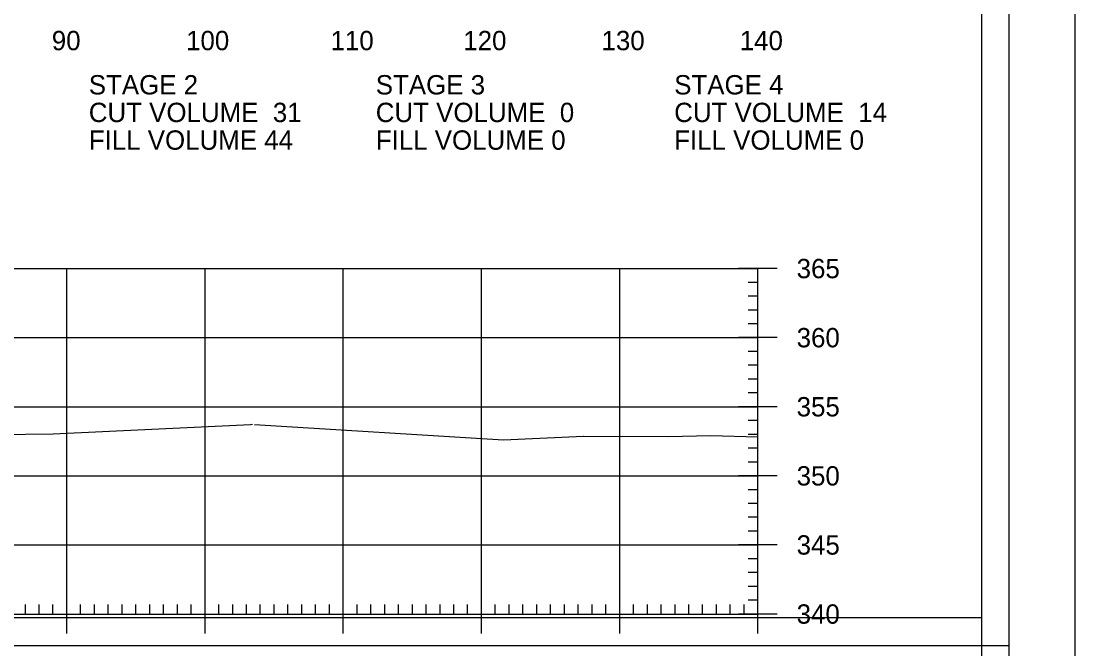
# Model space of a CAD drawing. Extents: x 1368910 to 1369601, y 380116 to 380950.
# Drawn here: x 1369524.3 to 1369600.5, y 380416.9 to 380462.3 of the extents above; entities that cross this region are included whole.
import ezdxf

# ---------------------------------------------------------------- set-up
doc = ezdxf.new("R2010")
doc.units = 0
for name, color, linetype in [('R_Axis', 7, 'Continuous'), ('R_Axis Annot', 7, 'Continuous'), ('R_Border', 7, 'Continuous'), ('R_Border Plan-Plan', 7, 'Continuous'), ('R_Exist Surface', 7, 'Continuous'), ('R_Grid', 7, 'Continuous'), ('R_No Plot', 7, 'Continuous')]:
    doc.layers.add(name, color=color, linetype=linetype)

msp = doc.modelspace()

# ---------------------------------------------------------------- linework, layer by layer
at = {"layer": 'R_Axis'}
for p, q in [((1369578.99, 380444.421), (1369576.19, 380444.421)), ((1369577.59, 380419.421), (1369577.59, 380444.421)), ((1369577.59, 380443.421), (1369576.89, 380443.421)), ((1369577.59, 380442.421), (1369576.89, 380442.421)), ((1369577.59, 380441.421), (1369576.89, 380441.421)), ((1369577.59, 380440.421), (1369576.89, 380440.421)), ((1369578.99, 380439.421), (1369576.19, 380439.421)), ((1369577.59, 380438.421), (1369576.89, 380438.421)), ((1369577.59, 380437.421), (1369576.89, 380437.421)), ((1369577.59, 380436.421), (1369576.89, 380436.421)), ((1369577.59, 380435.421), (1369576.89, 380435.421)), ((1369578.99, 380434.421), (1369576.19, 380434.421)), ((1369577.59, 380433.421), (1369576.89, 380433.421)), ((1369577.59, 380432.421), (1369576.89, 380432.421)), ((1369577.59, 380431.421), (1369576.89, 380431.421)), ((1369577.59, 380430.421), (1369576.89, 380430.421)), ((1369578.99, 380429.421), (1369576.19, 380429.421)), ((1369577.59, 380428.421), (1369576.89, 380428.421)), ((1369577.59, 380427.421), (1369576.89, 380427.421)), ((1369577.59, 380426.421), (1369576.89, 380426.421)), ((1369577.59, 380425.421), (1369576.89, 380425.421)), ((1369578.99, 380424.421), (1369576.19, 380424.421)), ((1369577.59, 380423.421), (1369576.89, 380423.421)), ((1369577.59, 380422.421), (1369576.89, 380422.421)), ((1369527.59, 380418.021), (1369527.59, 380420.821)), ((1369537.59, 380418.021), (1369537.59, 380420.821)), ((1369547.59, 380418.021), (1369547.59, 380420.821)), ((1369557.59, 380418.021), (1369557.59, 380420.821)), ((1369567.59, 380418.021), (1369567.59, 380420.821)), ((1369577.59, 380421.421), (1369576.89, 380421.421)), ((1369577.59, 380418.021), (1369577.59, 380420.821)), ((1369524.59, 380419.421), (1369524.59, 380420.121)), ((1369525.59, 380419.421), (1369525.59, 380420.121)), ((1369526.59, 380419.421), (1369526.59, 380420.121)), ((1369528.59, 380419.421), (1369528.59, 380420.121)), ((1369529.59, 380419.421), (1369529.59, 380420.121)), ((1369530.59, 380419.421), (1369530.59, 380420.121)), ((1369531.59, 380419.421), (1369531.59, 380420.121)), ((1369532.59, 380419.421), (1369532.59, 380420.121)), ((1369533.59, 380419.421), (1369533.59, 380420.121)), ((1369534.59, 380419.421), (1369534.59, 380420.121)), ((1369535.59, 380419.421), (1369535.59, 380420.121)), ((1369536.59, 380419.421), (1369536.59, 380420.121)), ((1369538.59, 380419.421), (1369538.59, 380420.121)), ((1369539.59, 380419.421), (1369539.59, 380420.121)), ((1369540.59, 380419.421), (1369540.59, 380420.121)), ((1369541.59, 380419.421), (1369541.59, 380420.121)), ((1369542.59, 380419.421), (1369542.59, 380420.121)), ((1369543.59, 380419.421), (1369543.59, 380420.121)), ((1369544.59, 380419.421), (1369544.59, 380420.121)), ((1369545.59, 380419.421), (1369545.59, 380420.121)), ((1369546.59, 380419.421), (1369546.59, 380420.121)), ((1369548.59, 380419.421), (1369548.59, 380420.121)), ((1369549.59, 380419.421), (1369549.59, 380420.121)), ((1369550.59, 380419.421), (1369550.59, 380420.121)), ((1369551.59, 380419.421), (1369551.59, 380420.121)), ((1369552.59, 380419.421), (1369552.59, 380420.121)), ((1369553.59, 380419.421), (1369553.59, 380420.121)), ((1369554.59, 380419.421), (1369554.59, 380420.121)), ((1369555.59, 380419.421), (1369555.59, 380420.121)), ((1369556.59, 380419.421), (1369556.59, 380420.121)), ((1369558.59, 380419.421), (1369558.59, 380420.121)), ((1369559.59, 380419.421), (1369559.59, 380420.121)), ((1369560.59, 380419.421), (1369560.59, 380420.121)), ((1369561.59, 380419.421), (1369561.59, 380420.121)), ((1369562.59, 380419.421), (1369562.59, 380420.121)), ((1369563.59, 380419.421), (1369563.59, 380420.121)), ((1369564.59, 380419.421), (1369564.59, 380420.121)), ((1369565.59, 380419.421), (1369565.59, 380420.121)), ((1369566.59, 380419.421), (1369566.59, 380420.121)), ((1369568.59, 380419.421), (1369568.59, 380420.121)), ((1369569.59, 380419.421), (1369569.59, 380420.121)), ((1369570.59, 380419.421), (1369570.59, 380420.121)), ((1369571.59, 380419.421), (1369571.59, 380420.121)), ((1369572.59, 380419.421), (1369572.59, 380420.121)), ((1369573.59, 380419.421), (1369573.59, 380420.121)), ((1369574.59, 380419.421), (1369574.59, 380420.121)), ((1369575.59, 380419.421), (1369575.59, 380420.121)), ((1369576.59, 380419.421), (1369576.59, 380420.121)), ((1369577.59, 380420.421), (1369576.89, 380420.421)), ((1369297.59, 380419.421), (1369577.59, 380419.421)), ((1369578.99, 380419.421), (1369576.19, 380419.421))]:
    msp.add_line(p, q, dxfattribs=at)
at = {"layer": 'R_Border'}
msp.add_line((1369595.77, 380314.421), (1369595.77, 380519.881), dxfattribs=at)
at = {"layer": 'R_Border Plan-Plan'}
msp.add_line((1369279.59, 380417.151), (1369595.77, 380417.151), dxfattribs=at)
at = {"layer": 'R_Exist Surface'}
for points in [[(1369520.598, 380432.384), (1369526.613, 380432.459), (1369540.883, 380433.141), (1369541.034, 380433.151)], [(1369541.174, 380433.14), (1369559.175, 380432.028), (1369564.982, 380432.281), (1369564.993, 380432.281), (1369571.094, 380432.27), (1369574.193, 380432.335), (1369577.59, 380432.243)]]:
    msp.add_lwpolyline(points, dxfattribs=at)
at = {"layer": 'R_Grid'}
for p, q in [((1369297.59, 380444.421), (1369577.59, 380444.421)), ((1369297.59, 380444.421), (1369577.59, 380444.421)), ((1369527.59, 380419.421), (1369527.59, 380444.421)), ((1369527.59, 380419.421), (1369527.59, 380444.421)), ((1369537.59, 380419.421), (1369537.59, 380444.421)), ((1369537.59, 380419.421), (1369537.59, 380444.421)), ((1369547.59, 380419.421), (1369547.59, 380444.421)), ((1369547.59, 380419.421), (1369547.59, 380444.421)), ((1369557.59, 380419.421), (1369557.59, 380444.421)), ((1369557.59, 380419.421), (1369557.59, 380444.421)), ((1369567.59, 380419.421), (1369567.59, 380444.421)), ((1369567.59, 380419.421), (1369567.59, 380444.421)), ((1369577.59, 380419.421), (1369577.59, 380444.421)), ((1369577.59, 380419.421), (1369577.59, 380444.421)), ((1369297.59, 380439.421), (1369577.59, 380439.421)), ((1369297.59, 380439.421), (1369577.59, 380439.421)), ((1369297.59, 380434.421), (1369577.59, 380434.421)), ((1369297.59, 380434.421), (1369577.59, 380434.421)), ((1369297.59, 380429.421), (1369577.59, 380429.421)), ((1369297.59, 380429.421), (1369577.59, 380429.421)), ((1369297.59, 380424.421), (1369577.59, 380424.421)), ((1369297.59, 380424.421), (1369577.59, 380424.421)), ((1369297.59, 380419.421), (1369577.59, 380419.421)), ((1369297.59, 380419.421), (1369577.59, 380419.421))]:
    msp.add_line(p, q, dxfattribs=at)
at = {"layer": 'R_No Plot'}
for points in [[(1369267.182, 380523.775), (1369600.522, 380523.775), (1369600.522, 380310.438), (1369267.182, 380310.438)], [(1369593.77, 380419.151), (1369281.59, 380419.151), (1369281.59, 380517.881), (1369531.13, 380517.881), (1369531.13, 380508.001), (1369548.67, 380508.001), (1369572.77, 380508.001), (1369572.77, 380485.668), (1369593.77, 380485.668)], [(1369281.59, 380517.881), (1369531.13, 380517.881), (1369531.13, 380508.001), (1369548.67, 380508.001), (1369572.77, 380508.001), (1369572.77, 380485.668), (1369593.77, 380485.668), (1369593.77, 380316.421), (1369281.59, 380316.421)]]:
    msp.add_lwpolyline(points, close=True, dxfattribs=at)

# ---------------------------------------------------------------- texts
at = {"layer": 'R_Axis Annot'}
for s, p in [('90', (1369526.504, 380460.221)), ('100', (1369536.218, 380460.221)), ('110', (1369546.67, 380460.221)), ('120', (1369556.273, 380460.221)), ('130', (1369566.273, 380460.221)), ('140', (1369576.273, 380460.221)), ('STAGE 2', (1369529.18, 380457.021)), ('STAGE 3', (1369549.942, 380457.021)), ('STAGE 4', (1369571.532, 380457.021)), ('CUT VOLUME  31', (1369529.18, 380455.021)), ('CUT VOLUME  0', (1369549.942, 380455.021)), ('CUT VOLUME  14', (1369571.532, 380455.021)), ('FILL VOLUME 44', (1369529.18, 380453.021)), ('FILL VOLUME 0', (1369549.942, 380453.021)), ('FILL VOLUME 0', (1369571.532, 380453.021)), ('365', (1369580.39, 380443.721)), ('360', (1369580.39, 380438.721)), ('355', (1369580.39, 380433.721)), ('350', (1369580.39, 380428.721)), ('345', (1369580.39, 380423.721)), ('340', (1369580.39, 380418.721))]:
    msp.add_text(s, height=1.4, dxfattribs=at).set_placement(p)

doc.saveas('drawing.dxf')
